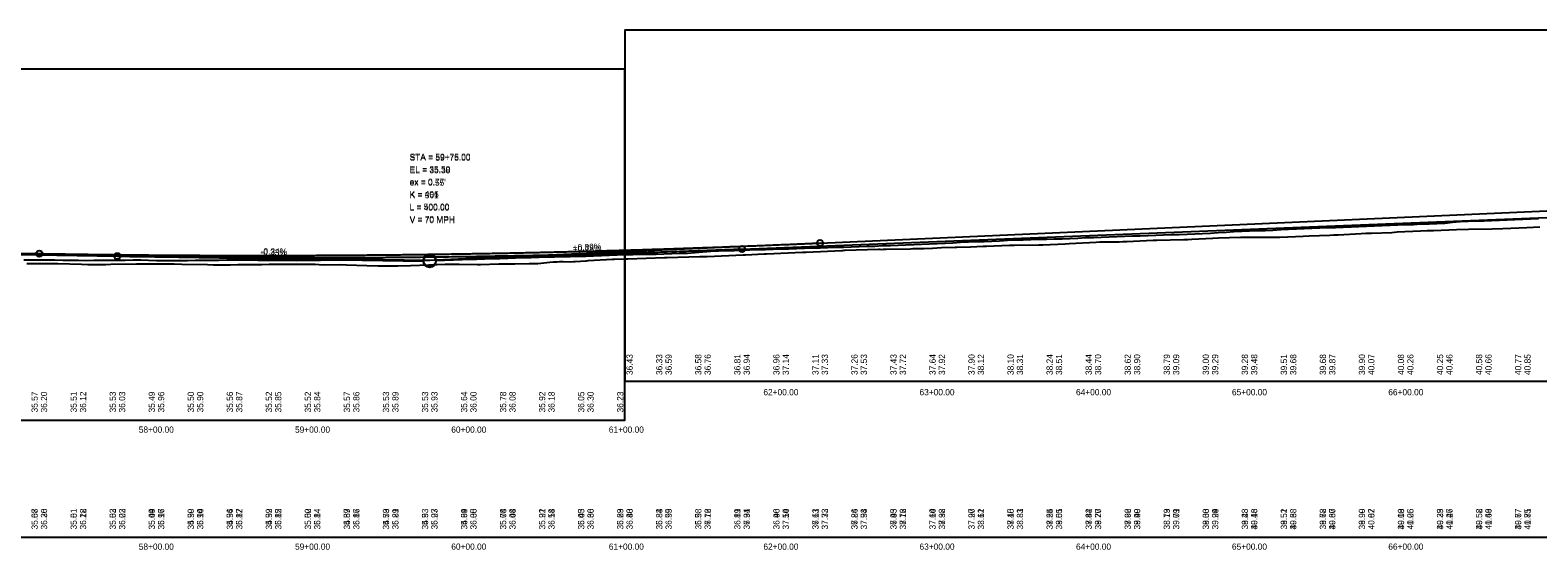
# Model space of a CAD drawing. Extents: x 3880794 to 3915434, y 287517 to 300173.
# Drawn here: x 3886257 to 3887223, y 297716 to 298049 of the extents above; entities that cross this region are included whole.
import ezdxf

# ---------------------------------------------------------------- set-up
doc = ezdxf.new("R2010")
doc.units = 0
for name, color, linetype in [('Level 1', 7, 'Continuous'), ('Level 2', 7, 'Continuous'), ('Level 30', 7, 'Continuous'), ('Level 31', 7, 'Continuous'), ('Level 32', 7, 'Continuous'), ('Level 62', 7, 'Continuous'), ('Level 63', 7, 'Continuous')]:
    doc.layers.add(name, color=color, linetype=linetype)

msp = doc.modelspace()

# ---------------------------------------------------------------- linework, layer by layer
at = {"layer": 'Level 1'}
for p, q in [((3886713.3, 297908.91), (3887288.3, 297931.38)), ((3886038.3, 297908.85), (3886313.3, 297904.36)), ((3886313.3, 297904.36), (3886509.3, 297901.16)), ((3886713.3, 297908.91), (3886517.29, 297901.25))]:
    msp.add_line(p, q, dxfattribs=at)
for points in [[(3886777.28, 297908.05), (3886777.93, 297908.06), (3886778.65, 297908.1), (3886779.46, 297908.17), (3886800.69, 297908.73), (3886801.5, 297908.76), (3886802.48, 297908.71), (3886803.73, 297908.73), (3886805.53, 297908.8), (3886821.22, 297909.13), (3886822.8, 297909.25), (3886825.32, 297909.23), (3886829.99, 297909.15), (3886835.19, 297909.4), (3886841.06, 297909.94), (3886849.7, 297910.08), (3886850.95, 297910.15), (3886859.58, 297910.4), (3886867.68, 297910.71), (3886869.92, 297910.78), (3886884.64, 297911.35), (3886887.72, 297911.45), (3886903.31, 297911.5), (3886905.9, 297911.55), (3886920.29, 297912.32), (3886922.81, 297912.42), (3886940.16, 297913.37), (3886942.47, 297913.5), (3886954.89, 297913.57), (3886957.16, 297913.72), (3886959.74, 297913.81), (3886976.66, 297914.58), (3886979.02, 297914.64), (3886996.27, 297915.05), (3886998.79, 297915.11), (3887001.42, 297915.21), (3887014.73, 297915.94), (3887018.4, 297916), (3887032.54, 297916.52), (3887036.17, 297916.61), (3887052.03, 297916.45), (3887057.62, 297916.6), (3887072.72, 297917.13), (3887076.51, 297917.27), (3887089.83, 297917.83), (3887092.35, 297917.91), (3887095.17, 297918.08), (3887109.82, 297918.89), (3887112.73, 297919.11), (3887116.46, 297919.17), (3887129.49, 297919.58), (3887132.79, 297919.89), (3887147.82, 297920.59), (3887151.97, 297920.69), (3887156.13, 297920.88), (3887170.81, 297921.41), (3887178.64, 297921.59), (3887193.73, 297921.87), (3887200.58, 297922.03), (3887215.89, 297922.63), (3887224.27, 297923.17)], [(3886255.33, 297899.63), (3886270.26, 297899.55), (3886275.11, 297899.54), (3886290.35, 297899.19), (3886294.42, 297898.98), (3886299.85, 297899), (3886305.8, 297899.02), (3886309.07, 297899.28), (3886325.47, 297899.35), (3886329.92, 297899.37), (3886335.28, 297899.37), (3886349.68, 297899.51), (3886354.67, 297899.31), (3886370.93, 297898.98), (3886374.88, 297898.82), (3886379.51, 297898.81), (3886385.58, 297898.82), (3886390.44, 297898.92), (3886405.74, 297898.97), (3886410.39, 297899.14), (3886415.81, 297899.12), (3886427.73, 297899.15), (3886429.52, 297899.16), (3886431.64, 297899.18), (3886440.03, 297899.2), (3886444.98, 297898.85), (3886456.07, 297898.92), (3886459.94, 297898.72), (3886472.94, 297898.4), (3886480.39, 297898.23), (3886492.93, 297898.12), (3886501.1, 297898.35), (3886512.68, 297898.81), (3886513.02, 297898.82), (3886523.13, 297899.14), (3886532.15, 297899.28), (3886543.81, 297899.06), (3886545.77, 297899.09), (3886557.62, 297899.4), (3886566.49, 297899.41), (3886567.81, 297899.41), (3886576.92, 297899.65), (3886582.57, 297899.63), (3886590.24, 297900.47), (3886592.33, 297900.66), (3886594.83, 297900.8), (3886596.34, 297900.88), (3886598.67, 297900.94), (3886603.66, 297900.79), (3886605.48, 297900.83), (3886606.51, 297900.9), (3886613.27, 297901.32), (3886613.64, 297901.35), (3886614.88, 297901.48), (3886630.41, 297902.39), (3886631.54, 297902.43), (3886639.06, 297902.68), (3886640.13, 297902.66), (3886663.57, 297903.42), (3886664.11, 297903.41), (3886664.61, 297903.42), (3886665.13, 297903.42), (3886686.28, 297904.06), (3886686.86, 297904.05), (3886687.68, 297904.07), (3886690.2, 297904.17), (3886691.01, 297904.21), (3886713.97, 297905.17), (3886714.72, 297905.22), (3886715.56, 297905.25), (3886727.4, 297905.79), (3886728.22, 297905.8), (3886729.06, 297905.8), (3886752.07, 297906.84), (3886752.6, 297906.87), (3886753.28, 297906.9), (3886753.85, 297906.93), (3886754.46, 297906.93), (3886777.28, 297908.05)]]:
    msp.add_lwpolyline(points, dxfattribs=at)
msp.add_circle((3886513.3, 297901.09), 4, dxfattribs=at)
msp.add_spline([(3886313.3, 297904.36), (3886321.3, 297904.23), (3886329.3, 297904.12), (3886337.3, 297904.01), (3886345.3, 297903.91), (3886353.3, 297903.82), (3886361.3, 297903.73), (3886369.3, 297903.66), (3886377.3, 297903.6), (3886385.3, 297903.54), (3886393.3, 297903.49), (3886401.3, 297903.46), (3886409.3, 297903.43), (3886417.3, 297903.41), (3886425.3, 297903.4), (3886433.3, 297903.4), (3886441.3, 297903.4), (3886449.3, 297903.42), (3886457.3, 297903.44), (3886465.3, 297903.48), (3886473.3, 297903.52), (3886481.3, 297903.57), (3886489.3, 297903.63), (3886497.3, 297903.7), (3886505.3, 297903.78), (3886513.3, 297903.86), (3886521.3, 297903.96), (3886529.3, 297904.06), (3886537.3, 297904.17), (3886545.3, 297904.3), (3886553.3, 297904.43), (3886561.3, 297904.57), (3886569.3, 297904.72), (3886577.3, 297904.87), (3886585.3, 297905.04), (3886593.3, 297905.21), (3886601.3, 297905.4), (3886609.3, 297905.59), (3886617.3, 297905.79), (3886625.3, 297906), (3886633.3, 297906.22), (3886641.3, 297906.45), (3886649.3, 297906.69), (3886657.3, 297906.93), (3886665.3, 297907.19), (3886673.3, 297907.45), (3886681.3, 297907.73), (3886689.3, 297908.01), (3886697.3, 297908.3), (3886705.3, 297908.6), (3886713.3, 297908.91)], degree=3, dxfattribs=at)
at = {"layer": 'Level 2'}
for p, q in [((3886763.3, 297912.78), (3887238.3, 297933.85)), ((3886763.3, 297912.78), (3886517.29, 297901.87)), ((3885988.3, 297910.74), (3886263.3, 297906)), ((3886263.3, 297906), (3886509.3, 297901.76))]:
    msp.add_line(p, q, dxfattribs=at)
for points in [[(3887038.3, 297920.58), (3887043.3, 297920.69), (3887048.3, 297920.85), (3887053.3, 297921.04), (3887058.3, 297921.37), (3887063.3, 297921.72), (3887068.3, 297921.93), (3887073.3, 297922.08), (3887078.3, 297922.27), (3887083.3, 297922.45), (3887088.3, 297922.61), (3887093.3, 297922.77), (3887098.3, 297922.95), (3887103.3, 297923.13), (3887108.3, 297923.44), (3887113.3, 297923.67), (3887118.3, 297923.88), (3887123.3, 297924.1), (3887128.3, 297924.24), (3887133.3, 297924.41), (3887138.3, 297924.57), (3887143.3, 297924.72), (3887148.3, 297925.08), (3887153.3, 297925.07), (3887158.3, 297925.17), (3887163.3, 297925.45), (3887168.3, 297926.16), (3887173.3, 297926.55), (3887178.3, 297926.73), (3887183.3, 297926.9), (3887188.3, 297927.07), (3887193.3, 297927.23), (3887198.3, 297927.39), (3887203.3, 297927.54), (3887208.3, 297927.77), (3887213.3, 297928.03), (3887218.3, 297928.22), (3887223.3, 297928.42)], [(3886538.3, 297902.38), (3886543.3, 297902.51), (3886548.3, 297902.63), (3886553.3, 297902.76), (3886558.3, 297902.88), (3886563.3, 297903.08), (3886568.3, 297903.23), (3886573.3, 297903.4), (3886578.3, 297903.56), (3886583.3, 297903.73), (3886588.3, 297903.81), (3886593.3, 297903.92), (3886598.3, 297904.05), (3886603.3, 297904.17), (3886608.3, 297904.3), (3886613.3, 297904.42), (3886618.3, 297904.63), (3886623.3, 297904.83), (3886628.3, 297905.03), (3886633.3, 297905.23), (3886638.3, 297905.35), (3886643.3, 297905.44), (3886648.3, 297905.52), (3886653.3, 297905.61), (3886658.3, 297905.69), (3886663.3, 297905.86), (3886668.3, 297906.03), (3886673.3, 297906.27), (3886678.3, 297906.31), (3886683.3, 297906.66), (3886688.3, 297907.1), (3886693.3, 297907.47), (3886698.3, 297907.8), (3886703.3, 297907.97), (3886708.3, 297908.04), (3886713.3, 297908.27), (3886718.3, 297908.38), (3886723.3, 297908.52), (3886728.3, 297908.68), (3886733.3, 297908.85), (3886738.3, 297908.98), (3886743.3, 297909.11), (3886748.3, 297909.24), (3886753.3, 297909.38), (3886758.3, 297909.58), (3886763.3, 297909.73), (3886768.3, 297909.87), (3886773.3, 297910.02), (3886778.3, 297910.15), (3886783.3, 297910.27), (3886788.3, 297910.47), (3886793.3, 297910.66), (3886798.3, 297910.83), (3886803.3, 297911.08), (3886808.3, 297911.22), (3886813.3, 297911.36), (3886818.3, 297911.53), (3886823.3, 297911.75), (3886828.3, 297911.98), (3886833.3, 297912.21), (3886838.3, 297912.41), (3886843.3, 297912.69), (3886848.3, 297912.98), (3886853.3, 297913.25), (3886858.3, 297913.49), (3886863.3, 297913.67), (3886868.3, 297913.84), (3886873.3, 297914.03), (3886878.3, 297914.26), (3886883.3, 297914.49), (3886888.3, 297914.71), (3886893.3, 297914.91), (3886898.3, 297915.03), (3886903.3, 297915.17), (3886908.3, 297915.28), (3886913.3, 297915.4), (3886918.3, 297915.53), (3886923.3, 297915.68), (3886928.3, 297915.96), (3886933.3, 297916.24), (3886938.3, 297916.41), (3886943.3, 297916.52), (3886948.3, 297916.64), (3886953.3, 297916.91), (3886958.3, 297917.13), (3886963.3, 297917.29), (3886968.3, 297917.45), (3886973.3, 297917.62), (3886978.3, 297917.77), (3886983.3, 297917.95), (3886988.3, 297918.14), (3886993.3, 297918.33), (3886998.3, 297918.53), (3887003.3, 297918.74), (3887008.3, 297918.96), (3887013.3, 297919.18), (3887018.3, 297919.48), (3887023.3, 297919.8), (3887028.3, 297920.12), (3887033.3, 297920.44), (3887038.3, 297920.58)], [(3886253.3, 297901.95), (3886258.3, 297902.07), (3886263.3, 297902.06), (3886268.3, 297902.02), (3886273.3, 297901.9), (3886278.3, 297901.88), (3886283.3, 297901.86), (3886288.3, 297901.73), (3886293.3, 297901.63), (3886298.3, 297901.71), (3886303.3, 297901.79), (3886308.3, 297901.78), (3886313.3, 297901.82), (3886318.3, 297901.87), (3886323.3, 297901.92), (3886328.3, 297901.99), (3886333.3, 297901.82), (3886338.3, 297901.64), (3886343.3, 297901.47), (3886348.3, 297901.46), (3886353.3, 297901.54), (3886358.3, 297901.63), (3886363.3, 297901.71), (3886368.3, 297901.78), (3886373.3, 297901.83), (3886378.3, 297901.88), (3886383.3, 297901.93), (3886388.3, 297901.97), (3886393.3, 297901.94), (3886398.3, 297901.89), (3886403.3, 297901.84), (3886408.3, 297901.84), (3886413.3, 297901.8), (3886418.3, 297901.75), (3886423.3, 297901.7), (3886428.3, 297901.67), (3886433.3, 297901.72), (3886438.3, 297901.8), (3886443.3, 297901.84), (3886448.3, 297901.91), (3886453.3, 297901.99), (3886458.3, 297902.06), (3886463.3, 297902.06), (3886468.3, 297902.01), (3886473.3, 297902), (3886478.3, 297901.99), (3886483.3, 297901.97), (3886488.3, 297901.86), (3886493.3, 297901.83), (3886498.3, 297901.79), (3886503.3, 297901.76), (3886508.3, 297901.75), (3886513.3, 297901.84), (3886518.3, 297901.93), (3886523.3, 297902.02), (3886528.3, 297902.12), (3886533.3, 297902.21), (3886538.3, 297902.38)]]:
    msp.add_lwpolyline(points, dxfattribs=at)
for centre, radius in [((3886763.3, 297912.78), 2), ((3886263.3, 297906), 2), ((3886513.3, 297901.69), 4)]:
    msp.add_circle(centre, radius, dxfattribs=at)
msp.add_spline([(3886263.3, 297906), (3886273.3, 297905.84), (3886283.3, 297905.68), (3886293.3, 297905.54), (3886303.3, 297905.41), (3886313.3, 297905.29), (3886323.3, 297905.19), (3886333.3, 297905.1), (3886343.3, 297905.02), (3886353.3, 297904.95), (3886363.3, 297904.89), (3886373.3, 297904.85), (3886383.3, 297904.82), (3886393.3, 297904.8), (3886403.3, 297904.79), (3886413.3, 297904.8), (3886423.3, 297904.82), (3886433.3, 297904.85), (3886443.3, 297904.89), (3886453.3, 297904.95), (3886463.3, 297905.02), (3886473.3, 297905.1), (3886483.3, 297905.19), (3886493.3, 297905.29), (3886503.3, 297905.41), (3886513.3, 297905.54), (3886523.3, 297905.68), (3886533.3, 297905.84), (3886543.3, 297906), (3886553.3, 297906.18), (3886563.3, 297906.37), (3886573.3, 297906.58), (3886583.3, 297906.79), (3886593.3, 297907.02), (3886603.3, 297907.26), (3886613.3, 297907.51), (3886623.3, 297907.78), (3886633.3, 297908.05), (3886643.3, 297908.35), (3886653.3, 297908.65), (3886663.3, 297908.96), (3886673.3, 297909.29), (3886683.3, 297909.63), (3886693.3, 297909.98), (3886703.3, 297910.34), (3886713.3, 297910.72), (3886723.3, 297911.1), (3886733.3, 297911.51), (3886743.3, 297911.92), (3886753.3, 297912.34), (3886763.3, 297912.78)], degree=3, dxfattribs=at)
at = {"layer": 'Level 31'}
for centre in [(3886313.3, 297904.36), (3886713.3, 297908.91)]:
    msp.add_circle(centre, 2, dxfattribs=at)
at = {"layer": 'Level 62'}
for points in [[(3886638.3, 297824.19), (3887338.3, 297824.19), (3887338.3, 298049.19), (3886638.3, 298049.19)], [(3886638.3, 297824.19), (3887338.3, 297824.19), (3887338.3, 298049.19), (3886638.3, 298049.19)], [(3885938.3, 297799.19), (3886638.3, 297799.19), (3886638.3, 298024.19), (3885938.3, 298024.19)]]:
    msp.add_lwpolyline(points, close=True, dxfattribs=at)
at = {"layer": 'Level 63'}
msp.add_line((3881538.3, 297724.19), (3896411.35, 297724.19), dxfattribs=at)

# ---------------------------------------------------------------- texts
at = {"layer": 'Level 2'}
for s, p in [('STA = 59+75.00', (3886500.46, 297966.07)), ('EL = 35.50', (3886500.46, 297958.07)), ("ex = 0.77'", (3886500.46, 297950.07)), ('K = 406', (3886500.46, 297942.07)), ('L = 500.00', (3886500.46, 297934.07)), ('V = 70 MPH', (3886500.46, 297926.07))]:
    msp.add_text(s, height=4, dxfattribs=at).set_placement(p)
for s, rotation, p in [('+0.89%', 2.54018, (3886604.96, 297907.76)), ('-0.34%', 359.01224, (3886405.03, 297905.56))]:
    msp.add_text(s, height=4, rotation=rotation, dxfattribs=at).set_placement(p)
at = {"layer": 'Level 30'}
for s, p in [('62+00.00', (3886726.99, 297815.19)), ('62+00.00', (3886726.99, 297815.19)), ('63+00.00', (3886826.96, 297815.19)), ('64+00.00', (3886927.18, 297815.19)), ('64+00.00', (3886927.18, 297815.19)), ('65+00.00', (3887027.05, 297815.19)), ('65+00.00', (3887027.05, 297815.19)), ('66+00.00', (3887127.18, 297815.19)), ('66+00.00', (3887127.18, 297815.19)), ('58+00.00', (3886326.99, 297791.19)), ('58+00.00', (3886326.99, 297791.19)), ('59+00.00', (3886427.05, 297791.19)), ('59+00.00', (3886427.05, 297791.19)), ('60+00.00', (3886527.12, 297791.19)), ('60+00.00', (3886527.12, 297791.19)), ('61+00.00', (3886628, 297791.19)), ('61+00.00', (3886628, 297791.19)), ('58+00.00', (3886326.99, 297716.19)), ('58+00.00', (3886326.99, 297716.19)), ('59+00.00', (3886427.05, 297716.19)), ('59+00.00', (3886427.05, 297716.19)), ('60+00.00', (3886527.12, 297716.19)), ('60+00.00', (3886527.12, 297716.19)), ('61+00.00', (3886628, 297716.19)), ('61+00.00', (3886628, 297716.19)), ('62+00.00', (3886726.99, 297716.19)), ('62+00.00', (3886726.99, 297716.19)), ('63+00.00', (3886826.96, 297716.19)), ('63+00.00', (3886826.96, 297716.19)), ('64+00.00', (3886927.18, 297716.19)), ('64+00.00', (3886927.18, 297716.19)), ('65+00.00', (3887027.05, 297716.19)), ('65+00.00', (3887027.05, 297716.19)), ('66+00.00', (3887127.18, 297716.19)), ('66+00.00', (3887127.18, 297716.19))]:
    msp.add_text(s, height=4, dxfattribs=at).set_placement(p)
at = {"layer": 'Level 31'}
for s, p in [('STA = 59+75.00', (3886500.46, 297965.47)), ('EL = 35.38', (3886500.46, 297957.47)), ("ex = 0.55'", (3886500.46, 297949.47)), ('K = 361', (3886500.46, 297941.47)), ('L = 400.00', (3886500.46, 297933.47)), ('V = 70 MPH', (3886500.46, 297925.47))]:
    msp.add_text(s, height=4, dxfattribs=at).set_placement(p)
for s, rotation, p in [('-0.33%', 359.06359, (3886404.81, 297904.86)), ('+0.78%', 2.23781, (3886605.08, 297906.68)), ('36.43', 90, (3886643.3, 297828.19)), ('36.59', 90, (3886668.3, 297828.19)), ('36.76', 90, (3886693.3, 297828.19)), ('36.94', 90, (3886718.3, 297828.19)), ('37.14', 90, (3886743.3, 297828.19)), ('37.33', 90, (3886768.3, 297828.19)), ('37.53', 90, (3886793.3, 297828.19)), ('37.72', 90, (3886818.3, 297828.19)), ('37.92', 90, (3886843.3, 297828.19)), ('38.12', 90, (3886868.3, 297828.19)), ('38.31', 90, (3886893.3, 297828.19)), ('38.51', 90, (3886918.3, 297828.19)), ('38.70', 90, (3886943.3, 297828.19)), ('38.90', 90, (3886968.3, 297828.19)), ('39.09', 90, (3886993.3, 297828.19)), ('39.29', 90, (3887018.3, 297828.19)), ('39.48', 90, (3887043.3, 297828.19)), ('39.68', 90, (3887068.3, 297828.19)), ('39.87', 90, (3887093.3, 297828.19)), ('40.07', 90, (3887118.3, 297828.19)), ('40.26', 90, (3887143.3, 297828.19)), ('40.46', 90, (3887168.3, 297828.19)), ('40.66', 90, (3887193.3, 297828.19)), ('40.85', 90, (3887218.3, 297828.19)), ('36.20', 90, (3886268.3, 297804.19)), ('36.12', 90, (3886293.3, 297804.19)), ('36.03', 90, (3886318.3, 297804.19)), ('35.96', 90, (3886343.3, 297804.19)), ('35.90', 90, (3886368.3, 297804.19)), ('35.87', 90, (3886393.3, 297804.19)), ('35.85', 90, (3886418.3, 297804.19)), ('35.84', 90, (3886443.3, 297804.19)), ('35.86', 90, (3886468.3, 297804.19)), ('35.89', 90, (3886493.3, 297804.19)), ('35.93', 90, (3886518.3, 297804.19)), ('36.00', 90, (3886543.3, 297804.19)), ('36.08', 90, (3886568.3, 297804.19)), ('36.18', 90, (3886593.3, 297804.19)), ('36.30', 90, (3886618.3, 297804.19)), ('35.08', 90, (3886262.3, 297729.19)), ('36.20', 90, (3886268.3, 297729.19)), ('35.01', 90, (3886287.3, 297729.19)), ('36.12', 90, (3886293.3, 297729.19)), ('35.02', 90, (3886312.3, 297729.19)), ('36.03', 90, (3886318.3, 297729.19)), ('35.04', 90, (3886337.3, 297729.19)), ('35.96', 90, (3886343.3, 297729.19)), ('34.99', 90, (3886362.3, 297729.19)), ('35.90', 90, (3886368.3, 297729.19)), ('34.94', 90, (3886387.3, 297729.19)), ('35.87', 90, (3886393.3, 297729.19)), ('34.99', 90, (3886412.3, 297729.19)), ('35.85', 90, (3886418.3, 297729.19)), ('35.00', 90, (3886437.3, 297729.19)), ('35.84', 90, (3886443.3, 297729.19)), ('34.89', 90, (3886462.3, 297729.19)), ('35.86', 90, (3886468.3, 297729.19)), ('34.79', 90, (3886487.3, 297729.19)), ('35.89', 90, (3886493.3, 297729.19)), ('34.93', 90, (3886512.3, 297729.19)), ('35.93', 90, (3886518.3, 297729.19)), ('34.99', 90, (3886537.3, 297729.19)), ('36.00', 90, (3886543.3, 297729.19)), ('35.04', 90, (3886562.3, 297729.19)), ('36.08', 90, (3886568.3, 297729.19)), ('35.21', 90, (3886587.3, 297729.19)), ('36.18', 90, (3886593.3, 297729.19)), ('35.43', 90, (3886612.3, 297729.19)), ('36.30', 90, (3886618.3, 297729.19)), ('35.69', 90, (3886637.3, 297729.19)), ('36.43', 90, (3886643.3, 297729.19)), ('35.84', 90, (3886662.3, 297729.19)), ('36.59', 90, (3886668.3, 297729.19)), ('35.98', 90, (3886687.3, 297729.19)), ('36.76', 90, (3886693.3, 297729.19)), ('36.19', 90, (3886712.3, 297729.19)), ('36.94', 90, (3886718.3, 297729.19)), ('36.40', 90, (3886737.3, 297729.19)), ('37.14', 90, (3886743.3, 297729.19)), ('36.63', 90, (3886762.3, 297729.19)), ('37.33', 90, (3886768.3, 297729.19)), ('36.84', 90, (3886787.3, 297729.19)), ('37.53', 90, (3886793.3, 297729.19)), ('36.95', 90, (3886812.3, 297729.19)), ('37.72', 90, (3886818.3, 297729.19)), ('37.10', 90, (3886837.3, 297729.19)), ('37.92', 90, (3886843.3, 297729.19)), ('37.27', 90, (3886862.3, 297729.19)), ('38.12', 90, (3886868.3, 297729.19)), ('37.45', 90, (3886887.3, 297729.19)), ('38.31', 90, (3886893.3, 297729.19)), ('37.55', 90, (3886912.3, 297729.19)), ('38.51', 90, (3886918.3, 297729.19)), ('37.82', 90, (3886937.3, 297729.19)), ('38.70', 90, (3886943.3, 297729.19)), ('37.96', 90, (3886962.3, 297729.19)), ('38.90', 90, (3886968.3, 297729.19)), ('38.13', 90, (3886987.3, 297729.19)), ('39.09', 90, (3886993.3, 297729.19)), ('38.33', 90, (3887012.3, 297729.19)), ('39.29', 90, (3887018.3, 297729.19)), ('38.48', 90, (3887037.3, 297729.19)), ('39.48', 90, (3887043.3, 297729.19)), ('38.52', 90, (3887062.3, 297729.19)), ('39.68', 90, (3887068.3, 297729.19)), ('38.72', 90, (3887087.3, 297729.19)), ('39.87', 90, (3887093.3, 297729.19)), ('38.99', 90, (3887112.3, 297729.19)), ('40.07', 90, (3887118.3, 297729.19)), ('39.19', 90, (3887137.3, 297729.19)), ('40.26', 90, (3887143.3, 297729.19)), ('39.39', 90, (3887162.3, 297729.19)), ('40.46', 90, (3887168.3, 297729.19)), ('39.52', 90, (3887187.3, 297729.19)), ('40.66', 90, (3887193.3, 297729.19)), ('39.67', 90, (3887212.3, 297729.19)), ('40.85', 90, (3887218.3, 297729.19))]:
    msp.add_text(s, height=4, rotation=rotation, dxfattribs=at).set_placement(p)
at = {"layer": 'Level 32'}
for s, p in [('36.33', (3886662.3, 297828.19)), ('36.58', (3886687.3, 297828.19)), ('36.81', (3886712.3, 297828.19)), ('36.96', (3886737.3, 297828.19)), ('37.11', (3886762.3, 297828.19)), ('37.26', (3886787.3, 297828.19)), ('37.43', (3886812.3, 297828.19)), ('37.64', (3886837.3, 297828.19)), ('37.90', (3886862.3, 297828.19)), ('38.10', (3886887.3, 297828.19)), ('38.24', (3886912.3, 297828.19)), ('38.44', (3886937.3, 297828.19)), ('38.62', (3886962.3, 297828.19)), ('38.79', (3886987.3, 297828.19)), ('39.00', (3887012.3, 297828.19)), ('39.28', (3887037.3, 297828.19)), ('39.51', (3887062.3, 297828.19)), ('39.68', (3887087.3, 297828.19)), ('39.90', (3887112.3, 297828.19)), ('40.08', (3887137.3, 297828.19)), ('40.25', (3887162.3, 297828.19)), ('40.58', (3887187.3, 297828.19)), ('40.77', (3887212.3, 297828.19)), ('35.57', (3886262.3, 297804.19)), ('35.51', (3886287.3, 297804.19)), ('35.53', (3886312.3, 297804.19)), ('35.49', (3886337.3, 297804.19)), ('35.50', (3886362.3, 297804.19)), ('35.56', (3886387.3, 297804.19)), ('35.52', (3886412.3, 297804.19)), ('35.52', (3886437.3, 297804.19)), ('35.57', (3886462.3, 297804.19)), ('35.53', (3886487.3, 297804.19)), ('35.53', (3886512.3, 297804.19)), ('35.64', (3886537.3, 297804.19)), ('35.78', (3886562.3, 297804.19)), ('35.92', (3886587.3, 297804.19)), ('36.05', (3886612.3, 297804.19)), ('36.23', (3886637.3, 297804.19)), ('35.57', (3886262.3, 297729.19)), ('36.36', (3886268.3, 297729.19)), ('35.51', (3886287.3, 297729.19)), ('36.28', (3886293.3, 297729.19)), ('35.53', (3886312.3, 297729.19)), ('36.22', (3886318.3, 297729.19)), ('35.49', (3886337.3, 297729.19)), ('36.17', (3886343.3, 297729.19)), ('35.50', (3886362.3, 297729.19)), ('36.14', (3886368.3, 297729.19)), ('35.56', (3886387.3, 297729.19)), ('36.12', (3886393.3, 297729.19)), ('35.52', (3886412.3, 297729.19)), ('36.12', (3886418.3, 297729.19)), ('35.52', (3886437.3, 297729.19)), ('36.14', (3886443.3, 297729.19)), ('35.57', (3886462.3, 297729.19)), ('36.17', (3886468.3, 297729.19)), ('35.53', (3886487.3, 297729.19)), ('36.21', (3886493.3, 297729.19)), ('35.53', (3886512.3, 297729.19)), ('36.27', (3886518.3, 297729.19)), ('35.64', (3886537.3, 297729.19)), ('36.35', (3886543.3, 297729.19)), ('35.78', (3886562.3, 297729.19)), ('36.44', (3886568.3, 297729.19)), ('35.92', (3886587.3, 297729.19)), ('36.54', (3886593.3, 297729.19)), ('36.05', (3886612.3, 297729.19)), ('36.66', (3886618.3, 297729.19)), ('36.23', (3886637.3, 297729.19)), ('36.80', (3886643.3, 297729.19)), ('36.33', (3886662.3, 297729.19)), ('36.95', (3886668.3, 297729.19)), ('36.58', (3886687.3, 297729.19)), ('37.12', (3886693.3, 297729.19)), ('36.81', (3886712.3, 297729.19)), ('37.31', (3886718.3, 297729.19)), ('36.96', (3886737.3, 297729.19)), ('37.50', (3886743.3, 297729.19)), ('37.11', (3886762.3, 297729.19)), ('37.72', (3886768.3, 297729.19)), ('37.26', (3886787.3, 297729.19)), ('37.94', (3886793.3, 297729.19)), ('37.43', (3886812.3, 297729.19)), ('38.16', (3886818.3, 297729.19)), ('37.64', (3886837.3, 297729.19)), ('38.38', (3886843.3, 297729.19)), ('37.90', (3886862.3, 297729.19)), ('38.61', (3886868.3, 297729.19)), ('38.10', (3886887.3, 297729.19)), ('38.83', (3886893.3, 297729.19)), ('38.24', (3886912.3, 297729.19)), ('39.05', (3886918.3, 297729.19)), ('38.44', (3886937.3, 297729.19)), ('39.27', (3886943.3, 297729.19)), ('38.62', (3886962.3, 297729.19)), ('39.49', (3886968.3, 297729.19)), ('38.79', (3886987.3, 297729.19)), ('39.71', (3886993.3, 297729.19)), ('39.00', (3887012.3, 297729.19)), ('39.94', (3887018.3, 297729.19)), ('39.28', (3887037.3, 297729.19)), ('40.16', (3887043.3, 297729.19)), ('39.51', (3887062.3, 297729.19)), ('40.38', (3887068.3, 297729.19)), ('39.68', (3887087.3, 297729.19)), ('40.60', (3887093.3, 297729.19)), ('39.90', (3887112.3, 297729.19)), ('40.82', (3887118.3, 297729.19)), ('40.08', (3887137.3, 297729.19)), ('41.05', (3887143.3, 297729.19)), ('40.25', (3887162.3, 297729.19)), ('41.27', (3887168.3, 297729.19)), ('40.58', (3887187.3, 297729.19)), ('41.49', (3887193.3, 297729.19)), ('40.77', (3887212.3, 297729.19)), ('41.71', (3887218.3, 297729.19))]:
    msp.add_text(s, height=4, rotation=90, dxfattribs=at).set_placement(p)

doc.saveas('drawing.dxf')
